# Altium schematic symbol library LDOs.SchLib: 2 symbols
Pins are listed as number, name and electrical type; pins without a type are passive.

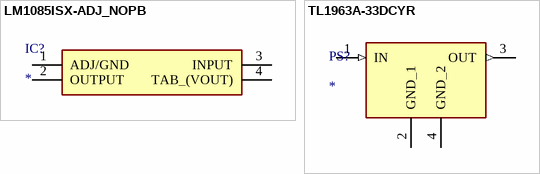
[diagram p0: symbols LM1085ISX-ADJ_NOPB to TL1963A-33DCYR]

## LM1085ISX-ADJ_NOPB
designator IC?
Integrated Circuit; Manufacturer_Name: Texas Instruments; Manufacturer_Part_Number: LM1085ISX-ADJ/NOPB; Description: 3A Fixed / Adjustable Output Linear Regulator
footprint KTT0003B
pins: 1 ADJ/GND, 2 OUTPUT, 3 INPUT, 4 TAB_(VOUT)

## TL1963A-33DCYR
designator PS?
Power Supply; Manufacturer_Name: Texas Instruments; Manufacturer_Part_Number: TL1963A-33DCYR
footprint SOT230P700X180-4N
pins: 1 IN (in), 2 GND_1 (power), 3 OUT (out), 4 GND_2 (power)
